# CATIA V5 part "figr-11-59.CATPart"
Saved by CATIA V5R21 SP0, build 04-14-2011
Part number: Part1
Bounding box of the stored display mesh (mm): x -59.829 to 59.829, y -71.429 to 72.174, z -61 to 76
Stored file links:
  D:\CATIA V5R21 E-RESOURCES\CATIA-V5R21\catia-v5r21-prt\c11-catia-v5r21-prt\c11-catia-v5r21-figr-11-59.CATPart
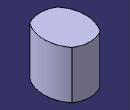
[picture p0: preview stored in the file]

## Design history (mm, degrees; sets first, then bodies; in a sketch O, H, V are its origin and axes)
Set1
  Extrude1: Element1 Sketch1, Lim1 76, Lim2 61, Direction xy-plane
Body1 (main body)
  Sketch1 on xy-plane, origin (0, 0, 0), H (0, 1, 0), V (-1, 0, 0)
    arc A1 centre (0, -40) radius 100 from (-60, 40) to (60, 40) cw
    point P2 (0, 60)
    point P3 (-60, 40)
    point P4 (60, 40)
    axis line L1 (-90, 0) -> (80, 0)
    point P6 (80, 0)
    point P7 (60, -40)
    point P8 (-60, -40)
    arc A2 centre (0, 40) radius 100 from (-60, -40) to (60, -40) ccw
    arc A3 centre (4.2857, 0) radius 75.7143 from (-60, 40) to (-60, -40) ccw
    arc A4 centre (0.3727, 0) radius 71.8012 from (60, -40) to (60, 40) ccw
    coincidence: A1 P2, P2 V, A3 P6
    horizontal: L1 H
    symmetry: P4 P7 L1, P3 P8 L1, A1 A2 L1
    tangency: A4 A3
  Sketch2 on xy-plane, origin (0, 0, 0), H (1, 0, 0), V (0, 1, 0)
    spline S1 through (80, 90) (60, 60) (70, 0) (50, -50) (50, -80)
    point P1 (70, 0)
    coincidence: P1 H
  CloseSurface1: CloseElement Extrude1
